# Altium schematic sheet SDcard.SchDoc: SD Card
size A4; Date: Not used; ApprovedBy: Not used; CheckedBy: Not used; Author: Not used; CompanyName: STMicroelectronics; DrawnBy: Not used; Engineer: Not used; Organization: Not used; Address1: Not used; Address2: Not used; Address3: Not used; Address4: Not used; DocumentNumber: Not used; Revision: Not used; SheetNumber: 9; SheetTotal: 23
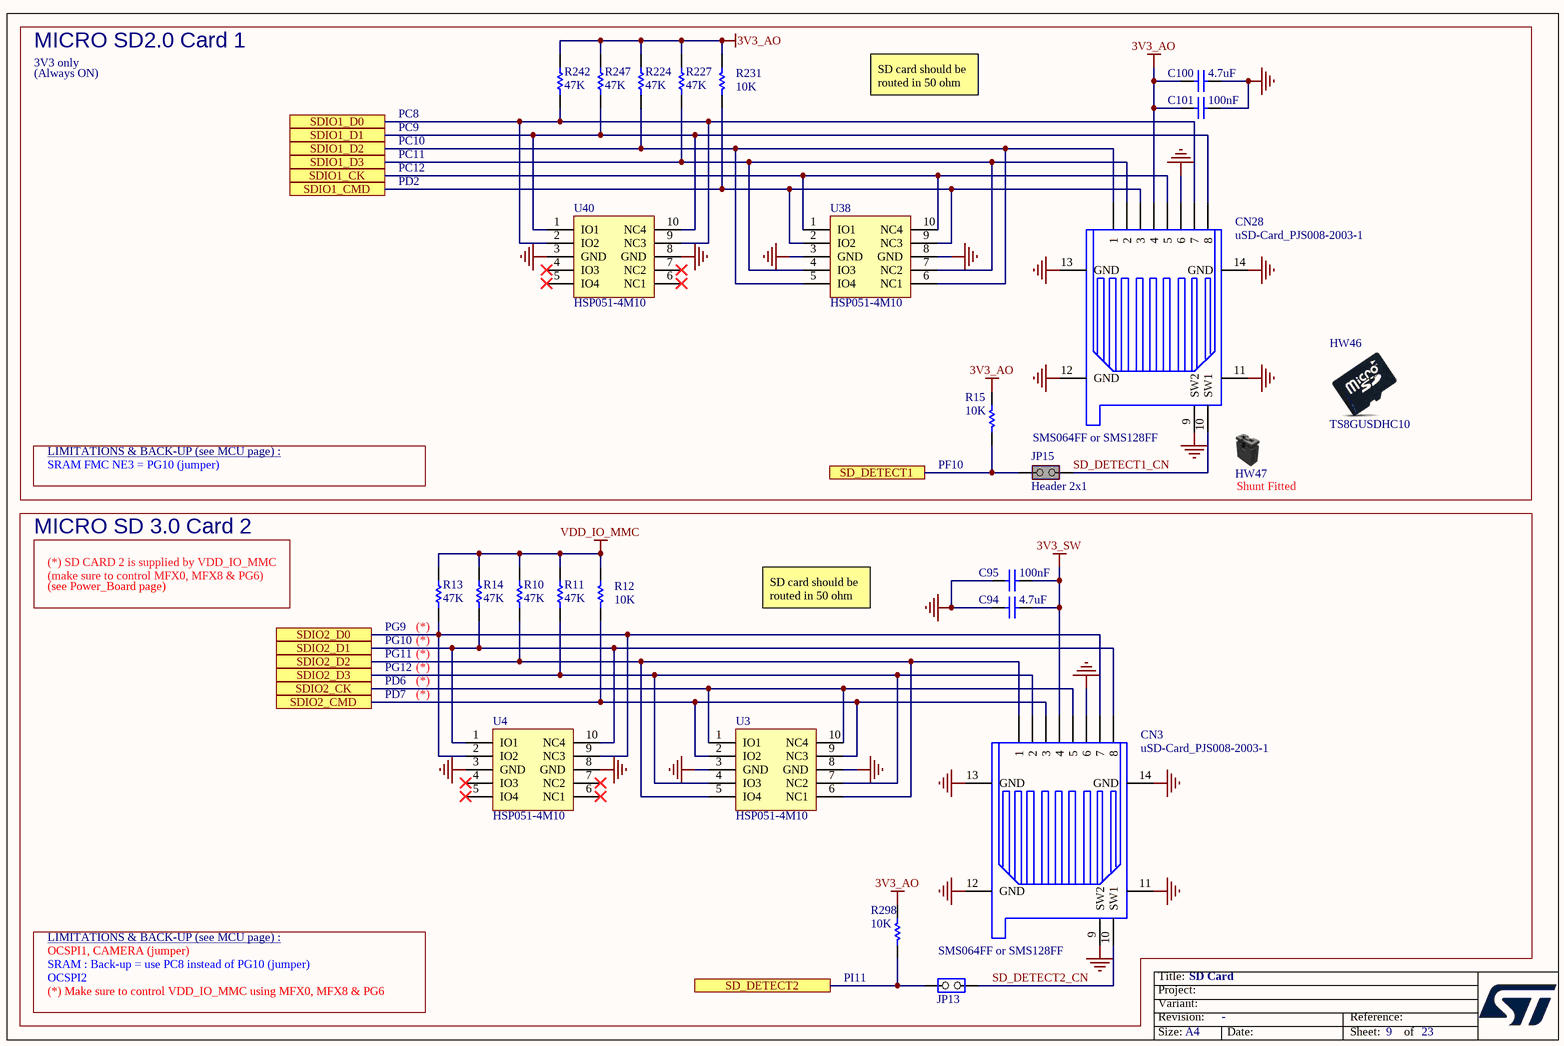
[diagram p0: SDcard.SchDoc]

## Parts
C94  value 4.7uF  [C0805]  (hidden comment: Capacitor)
C95  value 100nF  [C0402]  (hidden comment: Capacitor)
C100  value 4.7uF  [C0805]  (hidden comment: Capacitor)
C101  value 100nF  [C0402]  (hidden comment: Capacitor)
CN3  value uSD-Card_PJS008-2003-1  [CON_MICROSD_YAMAICHI_PJS008-2003-1]  (hidden comment: microSD-PJS008-2003)
CN28  value uSD-Card_PJS008-2003-1  [CON_MICROSD_YAMAICHI_PJS008-2003-1]  (hidden comment: microSD-PJS008-2003)
HW46  value TS8GUSDHC10  (hidden comment: Micro_SD_card)  (no BOM)
HW47  Shunt Black 2.54mm  (value not drawn)  (mechanical)
JP13  Jumper_Header 2x1  [CON_SAMTEC_TSW-102-07-G-S]  (value not drawn)
JP15  value Header 2x1  [CON_SAMTEC_TSW-102-07-G-S]  (hidden comment: Jumper_Header 2x1 Fitted)
R10  value 47K  [R0402]  (hidden comment: Resistor)
R11  value 47K  [R0402]  (hidden comment: Resistor)
R12  value 10K  [R0402]  (hidden comment: Resistor)
R13  value 47K  [R0402]  (hidden comment: Resistor)
R14  value 47K  [R0402]  (hidden comment: Resistor)
R15  value 10K  [R0402]  (hidden comment: Resistor)
R224  value 47K  [R0402]  (hidden comment: Resistor)
R227  value 47K  [R0402]  (hidden comment: Resistor)
R231  value 10K  [R0402]  (hidden comment: Resistor)
R242  value 47K  [R0402]  (hidden comment: Resistor)
R247  value 47K  [R0402]  (hidden comment: Resistor)
R298  value 10K  [R0402]  (hidden comment: Resistor)
U3  HSP051-4M10  [ESD_UQFN-10L_2P5X1_P050]
U4  HSP051-4M10  [ESD_UQFN-10L_2P5X1_P050]
U38  HSP051-4M10  [ESD_UQFN-10L_2P5X1_P050]
U40  HSP051-4M10  [ESD_UQFN-10L_2P5X1_P050]

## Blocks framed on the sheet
MICRO SD2.0 Card 1: C100 C101 CN28 HW46 HW47 JP15 R15 R224 R227 R231 R242 R247 U38 U40
MICRO SD 3.0 Card 2: C94 C95 CN3 JP13 R10-R14 R298 U3 U4

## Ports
SD_DETECT1, SD_DETECT2, SDIO1_CK, SDIO1_CMD, SDIO1_D0, SDIO1_D1, SDIO1_D2, SDIO1_D3, SDIO2_CK, SDIO2_CMD, SDIO2_D0, SDIO2_D1, SDIO2_D2, SDIO2_D3

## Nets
3V3_AO: C100.1 C101.1 CN28.4 R15.2 R224.2 R227.2 R231.2 R242.2 R247.2 R298.2
3V3_SW: C94.2 C95.2 CN3.4
GND: C94.1 C95.1 C100.2 C101.2 CN3.6 CN3.9(SW2) CN3.11(GND) CN3.12(GND) CN3.13(GND) CN3.14(GND) CN28.6 CN28.9(SW2) CN28.11(GND) CN28.12(GND) CN28.13(GND) CN28.14(GND) U3.3(GND) U3.8(GND) U4.3(GND) U4.8(GND) U38.3(GND) U38.8(GND) U40.3(GND) U40.8(GND)
VDD_IO_MMC: R10.2 R11.2 R12.2 R13.2 R14.2
SD_DETECT1: JP15.1(COMMON) R15.1 ; port SD_DETECT1
SD_DETECT1_CN: CN28.10(SW1) JP15.2(NO)
SD_DETECT2: JP13.2(NO) R298.1 ; port SD_DETECT2
SD_DETECT2_CN: CN3.10(SW1) JP13.1(COMMON)
SDIO1_CK: CN28.5 U38.1(IO1) U38.10(NC4) ; port SDIO1_CK
SDIO1_CMD: CN28.3 R231.1 U38.2(IO2) U38.9(NC3) ; port SDIO1_CMD
SDIO1_D0: CN28.7 R242.1 U40.2(IO2) U40.9(NC3) ; port SDIO1_D0
SDIO1_D1: CN28.8 R247.1 U40.1(IO1) U40.10(NC4) ; port SDIO1_D1
SDIO1_D2: CN28.1 R224.1 U38.5(IO4) U38.6(NC1) ; port SDIO1_D2
SDIO1_D3: CN28.2 R227.1 U38.4(IO3) U38.7(NC2) ; port SDIO1_D3
SDIO2_CK: CN3.5 U3.1(IO1) U3.10(NC4) ; port SDIO2_CK
SDIO2_CMD: CN3.3 R12.1 U3.2(IO2) U3.9(NC3) ; port SDIO2_CMD
SDIO2_D0: CN3.7 R13.1 U4.2(IO2) U4.9(NC3) ; port SDIO2_D0
SDIO2_D1: CN3.8 R14.1 U4.1(IO1) U4.10(NC4) ; port SDIO2_D1
SDIO2_D2: CN3.1 R10.1 U3.5(IO4) U3.6(NC1) ; port SDIO2_D2
SDIO2_D3: CN3.2 R11.1 U3.4(IO3) U3.7(NC2) ; port SDIO2_D3

Not connected (* = marked no-connect by the designer): U4 4(IO3)* 5(IO4)* 6(NC1)* 7(NC2)*; U40 4(IO3)* 5(IO4)* 6(NC1)* 7(NC2)*

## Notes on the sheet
- 3V3 only
- (Always ON)
- PC8
- SD card should be routed in 50 ohm
- PC9
- PC10
- PC11
- PD2
- PC12
- LIMITATIONS & BACK-UP (see MCU page) :
- SMS064FF or SMS128FF
- SRAM FMC NE3 = PG10 (jumper)
- (near R15) PF10
- (near HW47) Shunt Fitted
- (see Power_Board page)
- (*) SD CARD 2 is supplied by VDD_IO_MMC
  (make sure to control MFX0, MFX8 & PG6)
- (near R13) PG9
- (near R13) PG10
- (near R13) PG11
- (near R13) (*)
- (*)
- PG12
- PD6
- PD7
- SRAM : Back-up = use PC8 instead of PG10 (jumper)
- OCSPI1, CAMERA (jumper)
- OCSPI2
- (*) Make sure to control VDD_IO_MMC using MFX0, MFX8 & PG6
- (near R298) PI11

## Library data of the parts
C94 C100 = MCD-04042: Capacitor, MLCC, 4.7uF, 16V, X7R, 10%, 0805, T=1.25mm; Manufacturer_Part_Number: 885012207053; Manufacturer: WURTH ELEKTRONIK; Part_Preference: Recommended; Order_Code_RS: 181-3521P; Component_Country_Of_Origin: Taiwan; ShowFields: YES; ID: 6158
C95 C101 = MCD-00006: Capacitor, MLCC, 100nF, 16V, X7R, 10%, 0402, T=0.5mm; Manufacturer_Part_Number: CC0402KRX7R7BB104; Manufacturer: YAGEO; Alternate_Manufacturer_Part_Number: GCM155R71C104KA55D; Alternate_Manufacturer: MURATA; Part_Preference: Recommended; Partial_Alternate_Internal_Part_Number: MCD-03299; Provided_By: SUBCO; ECCN_US: EAR99; ECCN_EU: NEC; Component_Country_Of_Origin: China; ID: 2474; Order_Code_RS: 9402047; ShowFields: YES
CN3 CN28 = MCD-00023: MicroSD Card Conn, Reversed-Type, Mnt Push-Push, Positionning holes; Part_Type: Connector; Manufacturer_Part_Number: PJS008-2003-1; Manufacturer: YAMAICHI; Part_Preference: Recommended; Provided_By: SUBCO; Component_Country_Of_Origin: Unknown; ID: 2492; ShowFields: YES
HW46 = MCD-00673: 8GB microSDHC SD card Class 10; Part_Type: Accessory; Manufacturer: TRANSCEND; Alternate_Manufacturer_Part_Number: SFSD8192N3BM1TO-I-GE-2B1-STD; Alternate_Manufacturer: SWISSBIT; Part_Preference: Recommended; Provided_By: SUBCO; Component_Country_Of_Origin: Taiwan; ID: 3072; Order_Code_RS: 758-2607; ShowFields: YES
HW47 = MCD-00043: SHUNT 2.54mm BLACK; Part_Type: Misc; Manufacturer: SAMTEC; Alternate_Manufacturer_Part_Number: 316102S111A; Alternate_Manufacturer: JIUBABA; Full_Alternate_Internal_Part_Number: MCD-02388; Manufacturer_HQ_COO: Unknown; Part_Preference: Recommended; Partial_Alternate_Internal_Part_Number: MCD-01849; Value: SNT-100-BK-G; Provided_By: SUBCO; Alternate_EMS: A; Component_Country_Of_Origin: China, Costa Rica, Malaysia, USA, Vietnam; ID: 2551; Order_Code_RS: 158-7784; ShowFields: YES
JP13 = MCD-00045: Header, 2x1, 2,54mm, VR, TH, Height 5.84mm/2.54mm; Manufacturer_Part_Number: TSW-102-07-G-S; Manufacturer: SAMTEC; Part_Type: Connector; Alternate_Manufacturer_Part_Number: 313102S111116;313102S111116; Alternate_Manufacturer: JIUBABA; LIANYI; Full_Alternate_Internal_Part_Number: MCD-02390; Part_Preference: Recommended; Partial_Alternate_Internal_Part_Number: MCD-02957, MCD-03720; Provided_By: SUBCO; Component_Country_Of_Origin: China, Costa Rica, Malaysia, USA, Vietnam; ID: 2545; Order_Code_RS: 2505044; ShowFields: YES
JP15 = MCD-00683: Header, 2x1, 2,54mm, VR, TH, Height 5.84mm/2.54mm - Shunt Fitted by default; Part_Type: Connector; Manufacturer_Part_Number: TSW-102-07-G-S; Manufacturer: SAMTEC; Alternate_Manufacturer_Part_Number: 313102S111116; Alternate_Manufacturer: LIANYI; Full_Alternate_Internal_Part_Number: MCD-02389; Part_Preference: Recommended; Partial_Alternate_Internal_Part_Number: MCD-02957, MCD-03720; Provided_By: SUBCO; Component_Country_Of_Origin: China, Costa Rica, Malaysia, USA, Vietnam; ID: 3057; Order_Code_RS: 155-5312; ShowFields: YES
R10 R11 R13 R14 R224 R227 R242 R247 = MCD-00063: Resistor,47K,0402,1%,1/16W; Manufacturer_Part_Number: RC0402FR-0747KL; Manufacturer: YAGEO; Part_Preference: Recommended; Provided_By: SUBCO; ECCN_US: EAR99; ECCN_EU: NEC; Component_Country_Of_Origin: China; ID: 2528; Order_Code_RS: 9239430; ShowFields: YES
R12 R15 R231 R298 = MCD-00053: Resistor,10K,0402,1%,1/16W; Manufacturer_Part_Number: RC0402FR-0710KL; Manufacturer: YAGEO; BMS_Part_Number: 9131590; Part_Preference: Recommended; Provided_By: SUBCO; ECCN_US: EAR99; ECCN_EU: NEC; Component_Country_Of_Origin: China; ID: 2539; Order_Code_RS: 9239359; ShowFields: YES
U3 U4 U38 U40 = MCD-00667: 4-line ESD protection for high speed lines; Manufacturer: STMICROELECTRONICS; Part_Type: Diode; BMS_Part_Number: 9179041; Manufacturer_HQ_COO: EU; Part_Preference: Recommended; Provided_By: SUBCO with ST control; ECCN_US: EAR99; ECCN_EU: NEC; Component_Country_Of_Origin: Philippines; ID: 3081; ShowFields: YES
